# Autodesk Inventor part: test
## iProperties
Author: ***
Created: 2002-02
Part Number: test
Document SubType Name: Modeling
Designer: ***
Control State: 0
Master: False
Checked Out: False
PropertySet Name: Design Tracking Control
Shininess: 65.0
Angle Display Precision: 2
Document Length Units: 11269
Document Angle Units: 11283
Document Time Units: 11279
Document Mass Units: 11290
Document Length Units Precision: 3
Document Angle Units Precision: 2
Compacted: False
PropertySet Name: _Private Model Information
Density: 0.0
Volumn: 0.0
Area: 0.0
PropertySet Name: Model Information
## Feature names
1. Extrusion1
2. Hole1
3. Circular Pattern1
